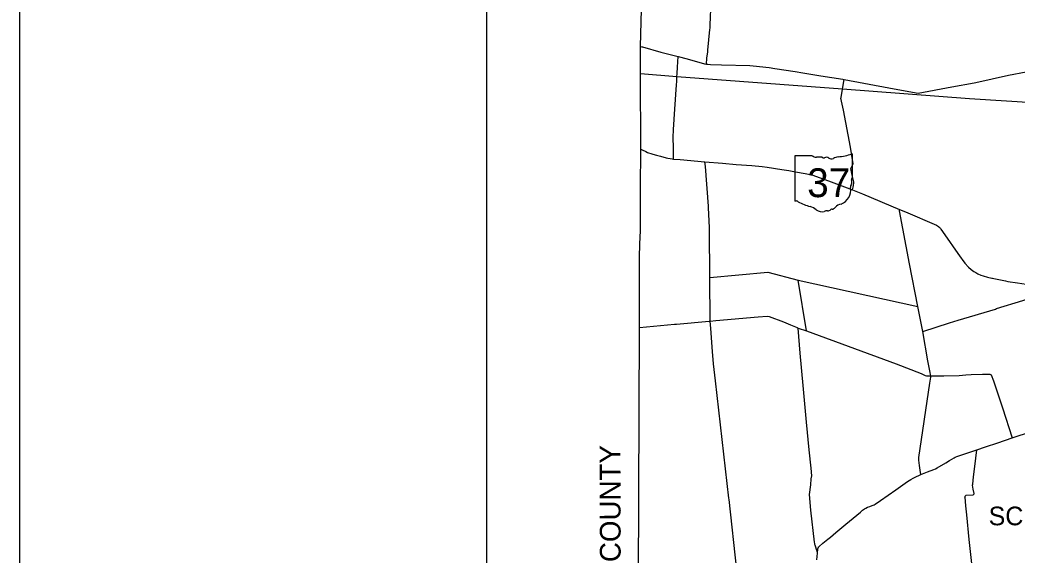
# Model space of a CAD drawing. Extents: x 1729596 to 1925846, y 659247 to 911751.
# Drawn here: x 1729596 to 1777664, y 833354 to 859172 of the extents above; entities that cross this region are included whole.
import ezdxf

# ---------------------------------------------------------------- set-up
doc = ezdxf.new("R2010")
doc.units = 0
for name, color, linetype in [('GM_X_Adjacent_County_Text', 7, 'Continuous'), ('GM_X_County', 7, 'Continuous'), ('GM_X_County_Road', 7, 'Continuous'), ('GM_X_State_Route', 7, 'Continuous'), ('GM_X_State_Shield', 7, 'Continuous'), ('GM_X_Township', 7, 'Continuous'), ('GM_X_Township_Road', 7, 'Continuous'), ('GM_X_Township_Text', 7, 'Continuous'), ('SC_Scratch1', 7, 'Continuous'), ('SH_Data', 7, 'Continuous')]:
    doc.layers.add(name, color=color, linetype=linetype)

msp = doc.modelspace()

# ---------------------------------------------------------------- linework, layer by layer
at = {"layer": 'GM_X_County'}
msp.add_lwpolyline([(1779378, 818146), (1775121, 818204), (1771439, 818234), (1765188, 818306), (1763158, 818312), (1762137, 818333), (1759879, 818354), (1759498, 818358), (1759475, 820549), (1759482, 825563), (1759416, 832152), (1759463, 844341), (1759463, 847793), (1759489, 848768), (1759505, 848913), (1759514, 851039), (1759526, 852942), (1759514, 856565), (1759518, 857896), (1759604, 861482)], dxfattribs=at)
at = {"layer": 'GM_X_County_Road'}
for points in [[(1759518, 857896), (1759574, 857878), (1759613, 857869), (1760488, 857624), (1761137, 857456), (1761330, 857415)], [(1761330, 857415), (1761757, 857293), (1762604, 857057), (1762687, 857045), (1762755, 857030), (1762889, 857019), (1763416, 856999), (1764783, 856969), (1764940, 856958), (1765711, 856869), (1765986, 856836), (1766962, 856678), (1767342, 856615), (1768207, 856468), (1769260, 856311), (1769327, 856301), (1771485, 855899), (1771485, 855899)], [(1774515, 855940), (1775597, 856145), (1775681, 856161), (1777256, 856513), (1778103, 856674), (1778201, 856693), (1778256, 856697), (1778340, 856696), (1778464, 856683)], [(1771485, 855899), (1772805, 855652), (1772899, 855634), (1774513, 855940), (1774515, 855940)], [(1764156, 832620), (1763784, 836032), (1763776, 836097), (1763123, 841759), (1763037, 842583), (1762977, 843169), (1762897, 844278), (1762874, 844646), (1762856, 846750), (1762837, 849052), (1762835, 849154), (1762790, 850103), (1762786, 850187), (1762639, 852096), (1762618, 852326)], [(1773032, 837243), (1772998, 837442), (1772959, 837683), (1772924, 837925), (1772923, 837966), (1772930, 838064), (1773454, 841640), (1773504, 841940), (1773503, 842000), (1773497, 842064), (1773475, 842168), (1773363, 842728), (1773117, 844144), (1772881, 845349), (1772483, 847403), (1771993, 849965), (1771991, 849978), (1771991, 849991), (1771992, 850005), (1771995, 850019), (1771999, 850032)], [(1768010, 833120), (1768038, 833441), (1768057, 833643), (1768064, 833677), (1768070, 833694), (1768077, 833710), (1768086, 833725), (1768100, 833745), (1768107, 833753), (1768123, 833768), (1768309, 833922), (1768539, 834113), (1768672, 834224), (1768934, 834445), (1769409, 834846), (1770122, 835431), (1770218, 835513), (1770267, 835551), (1770312, 835585), (1770373, 835622), (1770453, 835660), (1770565, 835703), (1770683, 835743), (1770769, 835781), (1770817, 835809), (1771078, 835986), (1771817, 836499), (1772388, 836896), (1772546, 837001), (1772648, 837060), (1772726, 837100), (1773032, 837243), (1773347, 837362), (1773655, 837477), (1773736, 837515), (1773814, 837558), (1774225, 837802), (1774410, 837914), (1774639, 838049), (1774684, 838071), (1774763, 838104), (1775098, 838217), (1775438, 838333), (1775724, 838433), (1776147, 838574), (1776742, 838771), (1777434, 839004), (1778366, 839322)]]:
    msp.add_lwpolyline(points, dxfattribs=at)
at = {"layer": 'GM_X_State_Route'}
for points in [[(1759526, 852942), (1759591, 852908), (1759768, 852824), (1759855, 852784), (1759903, 852765), (1760002, 852730), (1760102, 852701), (1760277, 852652), (1760476, 852596), (1760744, 852525), (1760828, 852502), (1760935, 852482), (1761034, 852468), (1761108, 852461), (1761421, 852437), (1762618, 852326), (1763459, 852257), (1764120, 852204), (1764882, 852142), (1765375, 852101), (1765612, 852072), (1766327, 851954), (1766657, 851900), (1766981, 851843), (1767455, 851763), (1767775, 851700), (1768574, 851406), (1769730, 850976), (1769888, 850917), (1770221, 850789), (1771999, 850032), (1772292, 849906), (1773777, 849265), (1773831, 849237), (1773877, 849206), (1773898, 849188), (1773937, 849150), (1773955, 849129), (1773972, 849107), (1773988, 849084), (1774185, 848807), (1774812, 847908), (1774968, 847684)], [(1774968, 847684), (1775017, 847613), (1775152, 847432), (1775319, 847250), (1775446, 847139), (1775582, 847039), (1775677, 846979), (1775773, 846927), (1775925, 846858), (1776029, 846819), (1776243, 846761), (1776454, 846715), (1776476, 846710)], [(1776476, 846710), (1776545, 846695), (1777099, 846577), (1777213, 846553), (1777679, 846483), (1778305, 846395), (1778834, 846323), (1779138, 846279), (1779232, 846271), (1779274, 846270), (1779424, 846274), (1779888, 846291), (1780260, 846299)]]:
    msp.add_lwpolyline(points, dxfattribs=at)
at = {"layer": 'GM_X_State_Shield'}
for p, q in [((1766947, 852586), (1766947, 850473)), ((1766947, 852586), (1766947, 850473)), ((1767790, 852623), (1766974, 852623)), ((1767790, 852623), (1766974, 852623)), ((1769731, 851569), (1769731, 852675)), ((1769731, 851569), (1769731, 852675)), ((1769731, 851570), (1769731, 851569)), ((1769731, 851570), (1769731, 851569))]:
    msp.add_line(p, q, dxfattribs=at)
for centre, radius, start, end in [((1766979, 852591), 32.3, 98.1301, 188.1301), ((1766979, 852591), 32.3, 98.1301, 188.1301), ((1767984, 852868), 313, 231.6195, 271.1119), ((1767984, 852868), 313, 231.6195, 271.1119), ((1768088, 851436), 1123, 80.4867, 94.9883), ((1768088, 851436), 1123, 80.4867, 94.9883), ((1768343, 852602), 90.3, 219.7921, 297.1024), ((1768343, 852602), 90.3, 219.7921, 297.1024), ((1768475, 852357), 188, 54.4667, 119.1411), ((1768475, 852357), 188, 54.4667, 119.1411), ((1768717, 852692), 226, 233.8562, 294.8282), ((1768717, 852692), 226, 233.8562, 294.8282), ((1769116, 851977), 594, 97.3462, 120.7689), ((1769116, 851977), 594, 97.3462, 120.7689), ((1768739, 855504), 2953, 275.8445, 288.9065), ((1768739, 855504), 2953, 275.8445, 288.9065), ((1769700, 852679), 31, 351.8621, 97.738), ((1769700, 852679), 31, 351.8621, 97.738), ((1769724, 851488), 48, 107.944, 210.337), ((1769724, 851488), 48, 107.944, 210.337), ((1769419, 851349), 288, 340.033, 23.6496), ((1769419, 851349), 288, 340.033, 23.6496), ((1769698, 851565), 33.2, 289.6038, 7.7341), ((1769698, 851565), 33.2, 289.6038, 7.7341), ((1768905, 850966), 739, 292.3089, 8.9858), ((1768905, 850966), 739, 292.3089, 8.9858), ((1769842, 851107), 210, 136.8065, 186.9296), ((1769842, 851107), 210, 136.8065, 186.9296), ((1766979, 850468), 32.5, 171.9584, 258.3066), ((1766979, 850468), 32.5, 171.9584, 258.3066), ((1766984, 850684), 248, 267.339, 280.6039), ((1766984, 850684), 248, 267.339, 280.6039), ((1767035, 850351), 89.5, 29.7484, 93.2717), ((1767035, 850351), 89.5, 29.7484, 93.2717), ((1768165, 852250), 2132, 240.4129, 257.1985), ((1768165, 852250), 2132, 240.4129, 257.1985), ((1767530, 849523), 667, 47.1842, 75.836), ((1767530, 849523), 667, 47.1842, 75.836), ((1768251, 850340), 423, 230.7004, 286.2918), ((1768251, 850340), 423, 230.7004, 286.2918), ((1768496, 849610), 348, 85.6951, 111.2099), ((1768496, 849610), 348, 85.6951, 111.2099), ((1768527, 850182), 226, 268.777, 315.5493), ((1768527, 850182), 226, 268.777, 315.5493), ((1768731, 849978), 63.5, 65.7517, 132.6484), ((1768731, 849978), 63.5, 65.7517, 132.6484), ((1768704, 850268), 239, 282.8732, 323.2771), ((1768704, 850268), 239, 282.8732, 323.2771), ((1769216, 849880), 404, 94.4031, 142.5768), ((1769216, 849880), 404, 94.4031, 142.5768)]:
    msp.add_arc(centre, radius, start, end, dxfattribs=at)
at = {"layer": 'GM_X_Township'}
msp.add_lwpolyline([(1778678, 855150), (1775377, 855361), (1769242, 855826), (1761265, 856432), (1759514, 856565)], dxfattribs=at)
at = {"layer": 'GM_X_Township_Road'}
for points in [[(1762687, 857045), (1762714, 857325), (1762752, 857634), (1762759, 857710), (1762857, 858709), (1762863, 858776), (1762892, 859462), (1762895, 859538), (1762893, 859960), (1762893, 860024), (1762945, 860602), (1762953, 860690), (1763076, 861845), (1763087, 861944), (1763086, 862049), (1763085, 862132)], [(1761259, 856255), (1761265, 856432), (1761271, 856584), (1761290, 856895), (1761330, 857415)], [(1761108, 852461), (1761107, 852748), (1761105, 852938), (1761109, 853081), (1761106, 853127), (1761082, 853368), (1761079, 853503), (1761097, 853880), (1761164, 854868), (1761246, 856040), (1761257, 856202), (1761259, 856255)], [(1769179, 855423), (1769242, 855826), (1769258, 855928), (1769327, 856301)], [(1769730, 850976), (1769768, 851110), (1769780, 851187), (1769790, 851318), (1769788, 851354), (1769715, 851685), (1769645, 852012), (1769767, 852228), (1769641, 853033), (1769298, 854816), (1769176, 855403), (1769177, 855414), (1769179, 855423)], [(1762856, 846750), (1765656, 846999), (1767114, 846620), (1772881, 845349)], [(1767508, 844174), (1767114, 846620)], [(1773117, 844144), (1774403, 844551), (1774819, 844683), (1776619, 845225), (1776675, 845242), (1777936, 845634), (1777990, 845650), (1779036, 846015), (1779423, 846131), (1779582, 846185), (1779752, 846241), (1779888, 846291)], [(1759463, 844341), (1761147, 844487), (1761246, 844496), (1762824, 844641), (1762874, 844646)], [(1762874, 844646), (1763140, 844664), (1765191, 844845), (1765624, 844879), (1765716, 844865), (1766402, 844601), (1766735, 844466), (1766824, 844428)], [(1766824, 844428), (1767061, 844328), (1767115, 844306), (1767508, 844174), (1771842, 842582), (1773043, 842113), (1773241, 842025), (1773292, 842008), (1773324, 842000), (1773359, 841996), (1773503, 842000), (1773908, 842003), (1774142, 842004), (1774870, 842013), (1775194, 842043), (1775452, 842064), (1776003, 842077), (1776186, 842079), (1776350, 842079), (1776414, 842051), (1776523, 841761), (1776957, 840456), (1777434, 839004)], [(1768038, 833441), (1768025, 833543), (1768017, 833568), (1767945, 833784), (1767930, 833832), (1767921, 833869), (1767913, 833906), (1767904, 833971), (1767729, 835522), (1767660, 836277), (1767716, 836738), (1767746, 837037), (1767769, 837171), (1767731, 837552), (1767649, 838423), (1767510, 839758), (1767352, 841532), (1767215, 843091), (1767115, 844306)], [(1775155, 836142), (1775154, 836154), (1775159, 836199), (1775188, 836235), (1775212, 836246), (1775541, 836263), (1775559, 836268), (1775582, 836287), (1775591, 836304), (1775593, 836332), (1775550, 836528), (1775530, 836630), (1775524, 836734), (1775526, 836776), (1775568, 837131), (1775643, 837758), (1775677, 838029), (1775724, 838433)], [(1775615, 831340), (1775603, 831383), (1775586, 831575), (1775490, 832941), (1775353, 834104), (1775241, 835291), (1775198, 835734), (1775155, 836142)]]:
    msp.add_lwpolyline(points, dxfattribs=at)
at = {"layer": 'SC_Scratch1'}
msp.add_lwpolyline([(1729596, 899996), (1925846, 899996), (1925846, 765496), (1729596, 765496)], close=True, dxfattribs=at)
at = {"layer": 'SH_Data'}
msp.add_line((1752099, 814428), (1752099, 890928), dxfattribs=at)

# ---------------------------------------------------------------- texts
at = {"layer": 'GM_X_Adjacent_County_Text'}
msp.add_text('UNION COUNTY', height=1000, rotation=90.0931, dxfattribs=at).set_placement((1758562, 828334))
at = {"layer": 'GM_X_State_Shield'}
msp.add_text('37', height=1392.2, dxfattribs=at).set_placement((1767548, 850622))
msp.add_text('37', height=1392.2, dxfattribs=at).set_placement((1767548, 850622))
at = {"layer": 'GM_X_Township_Text'}
msp.add_text('SCIOTO', height=900, rotation=0, dxfattribs=at).set_placement((1776295, 834791))

doc.saveas('drawing.dxf')
